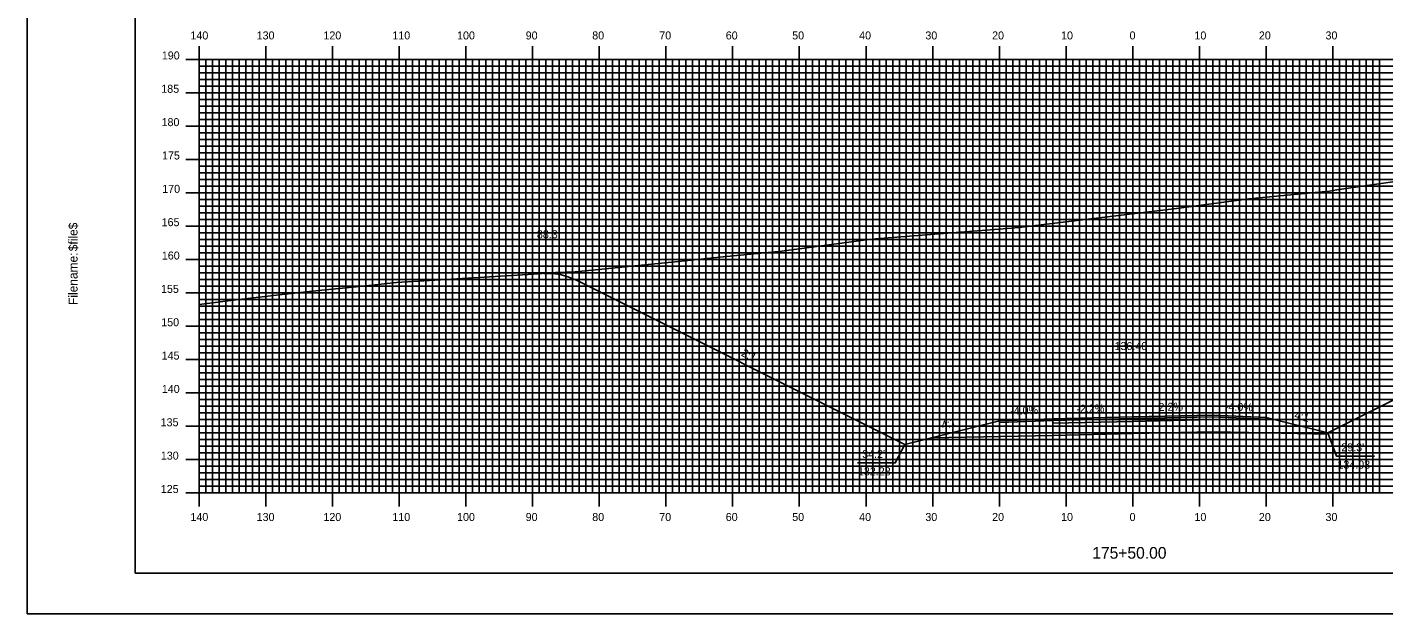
# Model space of a CAD drawing. Extents: x 1784221 to 1784564, y 442591 to 442811.
# Drawn here: x 1784221.2 to 1784424.7, y 442590.5 to 442678.5 of the extents above; entities that cross this region are included whole.
import ezdxf

# ---------------------------------------------------------------- set-up
doc = ezdxf.new("R2010")
doc.units = 0
for name, color, linetype in [('ANNOTATION', 7, 'Continuous'), ('BORDER', 7, 'Continuous'), ('D_Roadway_Centerline', 7, 'Continuous'), ('D_Roadway_Centerline_Text', 7, 'Continuous'), ('D_Roadway_Edge_Shoulder', 7, 'Continuous'), ('D_Roadway_Edge_TW', 7, 'Continuous'), ('D_Roadway_Pavement', 7, 'Continuous'), ('D_Roadway_SlopeLines', 7, 'Continuous'), ('D_Roadway_SubGrade', 7, 'Continuous'), ('D_Text_Standard', 7, 'Continuous'), ('H_V ANNOTATION', 7, 'Continuous'), ('MAJOR', 7, 'Continuous'), ('MINOR', 7, 'Continuous'), ('PLOT BOUNDARY', 7, 'Continuous'), ('S_Roadway_Centerline', 7, 'Continuous')]:
    doc.layers.add(name, color=color, linetype=linetype)

msp = doc.modelspace()

# ---------------------------------------------------------------- linework, layer by layer
at = {"layer": 'ANNOTATION'}
for points in [[(1784423.23, 442614.2), (1784417.54, 442614.2), (1784416.27, 442617.7)], [(1784345.7, 442613.18), (1784351.39, 442613.18), (1784352.83, 442615.94)]]:
    msp.add_lwpolyline(points, dxfattribs=at)
at = {"layer": 'BORDER'}
msp.add_lwpolyline([(1784237.4, 442596.67), (1784557.4, 442596.67), (1784557.4, 442806.67), (1784237.4, 442806.67)], close=True, dxfattribs=at)
at = {"layer": 'D_Roadway_Centerline'}
msp.add_lwpolyline([(1784298.69, 442641.6), (1784299.94, 442641.59), (1784301.19, 442641.41), (1784302.44, 442641.05), (1784303.69, 442640.51), (1784352.83, 442615.94), (1784356.83, 442616.94), (1784367, 442619.49), (1784375, 442619.81), (1784387, 442620.07), (1784399, 442620.33), (1784407, 442620.01), (1784416.27, 442617.7), (1784416.27, 442617.7), (1784509.11, 442664.11), (1784510.36, 442664.67), (1784511.61, 442665.1), (1784512.86, 442665.4), (1784514.11, 442665.56)], dxfattribs=at)
at = {"layer": 'D_Roadway_Edge_Shoulder'}
for points in [[(1784375, 442619.81), (1784367, 442619.49), (1784367, 442619.24), (1784375, 442619.56)], [(1784399, 442620.33), (1784407, 442620.01), (1784407, 442619.76), (1784399, 442620.08)]]:
    msp.add_lwpolyline(points, close=True, dxfattribs=at)
at = {"layer": 'D_Roadway_Edge_TW'}
msp.add_lwpolyline([(1784375, 442619.56), (1784375, 442619.81), (1784387, 442620.07), (1784399, 442620.33), (1784399, 442620.08), (1784387, 442619.82)], close=True, dxfattribs=at)
at = {"layer": 'D_Roadway_Pavement'}
msp.add_lwpolyline([(1784375, 442619.14), (1784375, 442619.56), (1784387, 442619.82), (1784399, 442620.08), (1784399, 442619.67), (1784387, 442619.4)], close=True, dxfattribs=at)
at = {"layer": 'D_Roadway_SlopeLines'}
for p in [(1784407, 442617.67), (1784416.27, 442617.7)]:
    msp.add_line(p, (1784416.27, 442617.49), dxfattribs=at)
for points in [[(1784416.27, 442617.7), (1784509.11, 442664.11), (1784510.36, 442664.67), (1784511.61, 442665.1), (1784512.86, 442665.4), (1784514.11, 442665.56)], [(1784352.83, 442615.94), (1784303.69, 442640.51), (1784302.44, 442641.05), (1784301.19, 442641.41), (1784299.94, 442641.59), (1784298.69, 442641.6)], [(1784367, 442619.49), (1784352.83, 442615.94)], [(1784407, 442620.01), (1784416.27, 442617.7)]]:
    msp.add_lwpolyline(points, dxfattribs=at)
at = {"layer": 'D_Roadway_SubGrade'}
msp.add_lwpolyline([(1784375, 442617.31), (1784356.83, 442616.94), (1784367, 442619.49), (1784367, 442619.24), (1784375, 442619.56), (1784387, 442619.82), (1784399, 442620.08), (1784407, 442619.76), (1784407, 442620.01), (1784407, 442617.67), (1784399, 442617.83), (1784387, 442617.57)], close=True, dxfattribs=at)
at = {"layer": 'MAJOR'}
for p, q in [((1784247, 442675.67), (1784247, 442673.67)), ((1784257, 442675.67), (1784257, 442673.67)), ((1784267, 442675.67), (1784267, 442673.67)), ((1784277, 442675.67), (1784277, 442673.67)), ((1784287, 442675.67), (1784287, 442673.67)), ((1784297, 442675.67), (1784297, 442673.67)), ((1784307, 442675.67), (1784307, 442673.67)), ((1784317, 442675.67), (1784317, 442673.67)), ((1784327, 442675.67), (1784327, 442673.67)), ((1784337, 442675.67), (1784337, 442673.67)), ((1784347, 442675.67), (1784347, 442673.67)), ((1784357, 442675.67), (1784357, 442673.67)), ((1784367, 442675.67), (1784367, 442673.67)), ((1784377, 442675.67), (1784377, 442673.67)), ((1784387, 442675.67), (1784387, 442673.67)), ((1784397, 442675.67), (1784397, 442673.67)), ((1784407, 442675.67), (1784407, 442673.67)), ((1784417, 442675.67), (1784417, 442673.67)), ((1784245, 442673.67), (1784247, 442673.67)), ((1784247, 442673.67), (1784527, 442673.67)), ((1784247, 442608.67), (1784247, 442673.67)), ((1784247, 442608.67), (1784247, 442673.67)), ((1784247, 442673.67), (1784527, 442673.67)), ((1784257, 442608.67), (1784257, 442673.67)), ((1784267, 442608.67), (1784267, 442673.67)), ((1784277, 442608.67), (1784277, 442673.67)), ((1784287, 442608.67), (1784287, 442673.67)), ((1784297, 442608.67), (1784297, 442673.67)), ((1784307, 442608.67), (1784307, 442673.67)), ((1784317, 442608.67), (1784317, 442673.67)), ((1784327, 442608.67), (1784327, 442673.67)), ((1784337, 442608.67), (1784337, 442673.67)), ((1784347, 442608.67), (1784347, 442673.67)), ((1784357, 442608.67), (1784357, 442673.67)), ((1784367, 442608.67), (1784367, 442673.67)), ((1784377, 442608.67), (1784377, 442673.67)), ((1784387, 442608.67), (1784387, 442673.67)), ((1784397, 442608.67), (1784397, 442673.67)), ((1784407, 442608.67), (1784407, 442673.67)), ((1784417, 442608.67), (1784417, 442673.67)), ((1784245, 442668.67), (1784247, 442668.67)), ((1784247, 442668.67), (1784527, 442668.67)), ((1784245, 442663.67), (1784247, 442663.67)), ((1784247, 442663.67), (1784527, 442663.67)), ((1784245, 442658.67), (1784247, 442658.67)), ((1784247, 442658.67), (1784527, 442658.67)), ((1784245, 442653.67), (1784247, 442653.67)), ((1784247, 442653.67), (1784527, 442653.67)), ((1784245, 442648.67), (1784247, 442648.67)), ((1784247, 442648.67), (1784527, 442648.67)), ((1784245, 442643.67), (1784247, 442643.67)), ((1784247, 442643.67), (1784527, 442643.67)), ((1784245, 442638.67), (1784247, 442638.67)), ((1784247, 442638.67), (1784527, 442638.67)), ((1784245, 442633.67), (1784247, 442633.67)), ((1784247, 442633.67), (1784527, 442633.67)), ((1784245, 442628.67), (1784247, 442628.67)), ((1784247, 442628.67), (1784527, 442628.67)), ((1784245, 442623.67), (1784247, 442623.67)), ((1784247, 442623.67), (1784527, 442623.67)), ((1784245, 442618.67), (1784247, 442618.67)), ((1784247, 442618.67), (1784527, 442618.67)), ((1784245, 442613.67), (1784247, 442613.67)), ((1784247, 442613.67), (1784527, 442613.67)), ((1784245, 442608.67), (1784247, 442608.67)), ((1784247, 442608.67), (1784527, 442608.67)), ((1784247, 442608.67), (1784527, 442608.67)), ((1784247, 442606.66), (1784247, 442608.67)), ((1784257, 442606.66), (1784257, 442608.67)), ((1784267, 442606.66), (1784267, 442608.67)), ((1784277, 442606.66), (1784277, 442608.67)), ((1784287, 442606.66), (1784287, 442608.67)), ((1784297, 442606.66), (1784297, 442608.67)), ((1784307, 442606.66), (1784307, 442608.67)), ((1784317, 442606.66), (1784317, 442608.67)), ((1784327, 442606.66), (1784327, 442608.67)), ((1784337, 442606.66), (1784337, 442608.67)), ((1784347, 442606.66), (1784347, 442608.67)), ((1784357, 442606.66), (1784357, 442608.67)), ((1784367, 442606.66), (1784367, 442608.67)), ((1784377, 442606.66), (1784377, 442608.67)), ((1784387, 442606.66), (1784387, 442608.67)), ((1784397, 442606.66), (1784397, 442608.67)), ((1784407, 442606.66), (1784407, 442608.67)), ((1784417, 442606.66), (1784417, 442608.67))]:
    msp.add_line(p, q, dxfattribs=at)
at = {"layer": 'MINOR'}
for p, q in [((1784248, 442608.67), (1784248, 442673.67)), ((1784249, 442608.67), (1784249, 442673.67)), ((1784250, 442608.67), (1784250, 442673.67)), ((1784251, 442608.67), (1784251, 442673.67)), ((1784252, 442608.67), (1784252, 442673.67)), ((1784253, 442608.67), (1784253, 442673.67)), ((1784254, 442608.67), (1784254, 442673.67)), ((1784255, 442608.67), (1784255, 442673.67)), ((1784256, 442608.67), (1784256, 442673.67)), ((1784258, 442608.67), (1784258, 442673.67)), ((1784259, 442608.67), (1784259, 442673.67)), ((1784260, 442608.67), (1784260, 442673.67)), ((1784261, 442608.67), (1784261, 442673.67)), ((1784262, 442608.67), (1784262, 442673.67)), ((1784263, 442608.67), (1784263, 442673.67)), ((1784264, 442608.67), (1784264, 442673.67)), ((1784265, 442608.67), (1784265, 442673.67)), ((1784266, 442608.67), (1784266, 442673.67)), ((1784268, 442608.67), (1784268, 442673.67)), ((1784269, 442608.67), (1784269, 442673.67)), ((1784270, 442608.67), (1784270, 442673.67)), ((1784271, 442608.67), (1784271, 442673.67)), ((1784272, 442608.67), (1784272, 442673.67)), ((1784273, 442608.67), (1784273, 442673.67)), ((1784274, 442608.67), (1784274, 442673.67)), ((1784275, 442608.67), (1784275, 442673.67)), ((1784276, 442608.67), (1784276, 442673.67)), ((1784278, 442608.67), (1784278, 442673.67)), ((1784279, 442608.67), (1784279, 442673.67)), ((1784280, 442608.67), (1784280, 442673.67)), ((1784281, 442608.67), (1784281, 442673.67)), ((1784282, 442608.67), (1784282, 442673.67)), ((1784283, 442608.67), (1784283, 442673.67)), ((1784284, 442608.67), (1784284, 442673.67)), ((1784285, 442608.67), (1784285, 442673.67)), ((1784286, 442608.67), (1784286, 442673.67)), ((1784288, 442608.67), (1784288, 442673.67)), ((1784289, 442608.67), (1784289, 442673.67)), ((1784290, 442608.67), (1784290, 442673.67)), ((1784291, 442608.67), (1784291, 442673.67)), ((1784292, 442608.67), (1784292, 442673.67)), ((1784293, 442608.67), (1784293, 442673.67)), ((1784294, 442608.67), (1784294, 442673.67)), ((1784295, 442608.67), (1784295, 442673.67)), ((1784296, 442608.67), (1784296, 442673.67)), ((1784298, 442608.67), (1784298, 442673.67)), ((1784299, 442608.67), (1784299, 442673.67)), ((1784300, 442608.67), (1784300, 442673.67)), ((1784301, 442608.67), (1784301, 442673.67)), ((1784302, 442608.67), (1784302, 442673.67)), ((1784303, 442608.67), (1784303, 442673.67)), ((1784304, 442608.67), (1784304, 442673.67)), ((1784305, 442608.67), (1784305, 442673.67)), ((1784306, 442608.67), (1784306, 442673.67)), ((1784308, 442608.67), (1784308, 442673.67)), ((1784309, 442608.67), (1784309, 442673.67)), ((1784310, 442608.67), (1784310, 442673.67)), ((1784311, 442608.67), (1784311, 442673.67)), ((1784312, 442608.67), (1784312, 442673.67)), ((1784313, 442608.67), (1784313, 442673.67)), ((1784314, 442608.67), (1784314, 442673.67)), ((1784315, 442608.67), (1784315, 442673.67)), ((1784316, 442608.67), (1784316, 442673.67)), ((1784318, 442608.67), (1784318, 442673.67)), ((1784319, 442608.67), (1784319, 442673.67)), ((1784320, 442608.67), (1784320, 442673.67)), ((1784321, 442608.67), (1784321, 442673.67)), ((1784322, 442608.67), (1784322, 442673.67)), ((1784323, 442608.67), (1784323, 442673.67)), ((1784324, 442608.67), (1784324, 442673.67)), ((1784325, 442608.67), (1784325, 442673.67)), ((1784326, 442608.67), (1784326, 442673.67)), ((1784328, 442608.67), (1784328, 442673.67)), ((1784329, 442608.67), (1784329, 442673.67)), ((1784330, 442608.67), (1784330, 442673.67)), ((1784331, 442608.67), (1784331, 442673.67)), ((1784332, 442608.67), (1784332, 442673.67)), ((1784333, 442608.67), (1784333, 442673.67)), ((1784334, 442608.67), (1784334, 442673.67)), ((1784335, 442608.67), (1784335, 442673.67)), ((1784336, 442608.67), (1784336, 442673.67)), ((1784338, 442608.67), (1784338, 442673.67)), ((1784339, 442608.67), (1784339, 442673.67)), ((1784340, 442608.67), (1784340, 442673.67)), ((1784341, 442608.67), (1784341, 442673.67)), ((1784342, 442608.67), (1784342, 442673.67)), ((1784343, 442608.67), (1784343, 442673.67)), ((1784344, 442608.67), (1784344, 442673.67)), ((1784345, 442608.67), (1784345, 442673.67)), ((1784346, 442608.67), (1784346, 442673.67)), ((1784348, 442608.67), (1784348, 442673.67)), ((1784349, 442608.67), (1784349, 442673.67)), ((1784350, 442608.67), (1784350, 442673.67)), ((1784351, 442608.67), (1784351, 442673.67)), ((1784352, 442608.67), (1784352, 442673.67)), ((1784353, 442608.67), (1784353, 442673.67)), ((1784354, 442608.67), (1784354, 442673.67)), ((1784355, 442608.67), (1784355, 442673.67)), ((1784356, 442608.67), (1784356, 442673.67)), ((1784358, 442608.67), (1784358, 442673.67)), ((1784359, 442608.67), (1784359, 442673.67)), ((1784360, 442608.67), (1784360, 442673.67)), ((1784361, 442608.67), (1784361, 442673.67)), ((1784362, 442608.67), (1784362, 442673.67)), ((1784363, 442608.67), (1784363, 442673.67)), ((1784364, 442608.67), (1784364, 442673.67)), ((1784365, 442608.67), (1784365, 442673.67)), ((1784366, 442608.67), (1784366, 442673.67)), ((1784368, 442608.67), (1784368, 442673.67)), ((1784369, 442608.67), (1784369, 442673.67)), ((1784370, 442608.67), (1784370, 442673.67)), ((1784371, 442608.67), (1784371, 442673.67)), ((1784372, 442608.67), (1784372, 442673.67)), ((1784373, 442608.67), (1784373, 442673.67)), ((1784374, 442608.67), (1784374, 442673.67)), ((1784375, 442608.67), (1784375, 442673.67)), ((1784376, 442608.67), (1784376, 442673.67)), ((1784378, 442608.67), (1784378, 442673.67)), ((1784379, 442608.67), (1784379, 442673.67)), ((1784380, 442608.67), (1784380, 442673.67)), ((1784381, 442608.67), (1784381, 442673.67)), ((1784382, 442608.67), (1784382, 442673.67)), ((1784383, 442608.67), (1784383, 442673.67)), ((1784384, 442608.67), (1784384, 442673.67)), ((1784385, 442608.67), (1784385, 442673.67)), ((1784386, 442608.67), (1784386, 442673.67)), ((1784388, 442608.67), (1784388, 442673.67)), ((1784389, 442608.67), (1784389, 442673.67)), ((1784390, 442608.67), (1784390, 442673.67)), ((1784391, 442608.67), (1784391, 442673.67)), ((1784392, 442608.67), (1784392, 442673.67)), ((1784393, 442608.67), (1784393, 442673.67)), ((1784394, 442608.67), (1784394, 442673.67)), ((1784395, 442608.67), (1784395, 442673.67)), ((1784396, 442608.67), (1784396, 442673.67)), ((1784398, 442608.67), (1784398, 442673.67)), ((1784399, 442608.67), (1784399, 442673.67)), ((1784400, 442608.67), (1784400, 442673.67)), ((1784401, 442608.67), (1784401, 442673.67)), ((1784402, 442608.67), (1784402, 442673.67)), ((1784403, 442608.67), (1784403, 442673.67)), ((1784404, 442608.67), (1784404, 442673.67)), ((1784405, 442608.67), (1784405, 442673.67)), ((1784406, 442608.67), (1784406, 442673.67)), ((1784408, 442608.67), (1784408, 442673.67)), ((1784409, 442608.67), (1784409, 442673.67)), ((1784410, 442608.67), (1784410, 442673.67)), ((1784411, 442608.67), (1784411, 442673.67)), ((1784412, 442608.67), (1784412, 442673.67)), ((1784413, 442608.67), (1784413, 442673.67)), ((1784414, 442608.67), (1784414, 442673.67)), ((1784415, 442608.67), (1784415, 442673.67)), ((1784416, 442608.67), (1784416, 442673.67)), ((1784418, 442608.67), (1784418, 442673.67)), ((1784419, 442608.67), (1784419, 442673.67)), ((1784420, 442608.67), (1784420, 442673.67)), ((1784421, 442608.67), (1784421, 442673.67)), ((1784422, 442608.67), (1784422, 442673.67)), ((1784423, 442608.67), (1784423, 442673.67)), ((1784424, 442608.67), (1784424, 442673.67)), ((1784247, 442672.67), (1784527, 442672.67)), ((1784247, 442672.67), (1784249, 442672.67)), ((1784247, 442671.67), (1784527, 442671.67)), ((1784247, 442671.67), (1784249, 442671.67)), ((1784247, 442670.67), (1784527, 442670.67)), ((1784247, 442670.67), (1784249, 442670.67)), ((1784247, 442669.67), (1784527, 442669.67)), ((1784247, 442669.67), (1784249, 442669.67)), ((1784247, 442667.67), (1784527, 442667.67)), ((1784247, 442667.67), (1784249, 442667.67)), ((1784247, 442666.67), (1784527, 442666.67)), ((1784247, 442666.67), (1784249, 442666.67)), ((1784247, 442665.67), (1784527, 442665.67)), ((1784247, 442665.67), (1784249, 442665.67)), ((1784247, 442664.67), (1784527, 442664.67)), ((1784247, 442664.67), (1784249, 442664.67)), ((1784247, 442662.67), (1784527, 442662.67)), ((1784247, 442662.67), (1784249, 442662.67)), ((1784247, 442661.67), (1784527, 442661.67)), ((1784247, 442661.67), (1784249, 442661.67)), ((1784247, 442660.67), (1784527, 442660.67)), ((1784247, 442660.67), (1784249, 442660.67)), ((1784247, 442659.67), (1784527, 442659.67)), ((1784247, 442659.67), (1784249, 442659.67)), ((1784247, 442657.67), (1784527, 442657.67)), ((1784247, 442657.67), (1784249, 442657.67)), ((1784247, 442656.67), (1784527, 442656.67)), ((1784247, 442656.67), (1784249, 442656.67)), ((1784247, 442655.67), (1784527, 442655.67)), ((1784247, 442655.67), (1784249, 442655.67)), ((1784247, 442654.67), (1784527, 442654.67)), ((1784247, 442654.67), (1784249, 442654.67)), ((1784247, 442652.67), (1784527, 442652.67)), ((1784247, 442652.67), (1784249, 442652.67)), ((1784247, 442651.67), (1784527, 442651.67)), ((1784247, 442651.67), (1784249, 442651.67)), ((1784247, 442650.67), (1784527, 442650.67)), ((1784247, 442650.67), (1784249, 442650.67)), ((1784247, 442649.67), (1784527, 442649.67)), ((1784247, 442649.67), (1784249, 442649.67)), ((1784247, 442647.67), (1784527, 442647.67)), ((1784247, 442647.67), (1784249, 442647.67)), ((1784247, 442646.67), (1784527, 442646.67)), ((1784247, 442646.67), (1784249, 442646.67)), ((1784247, 442645.67), (1784527, 442645.67)), ((1784247, 442645.67), (1784249, 442645.67)), ((1784247, 442644.67), (1784527, 442644.67)), ((1784247, 442644.67), (1784249, 442644.67)), ((1784247, 442642.67), (1784527, 442642.67)), ((1784247, 442642.67), (1784249, 442642.67)), ((1784247, 442641.67), (1784527, 442641.67)), ((1784247, 442641.67), (1784249, 442641.67)), ((1784247, 442640.67), (1784527, 442640.67)), ((1784247, 442640.67), (1784249, 442640.67)), ((1784247, 442639.67), (1784527, 442639.67)), ((1784247, 442639.67), (1784249, 442639.67)), ((1784247, 442637.67), (1784527, 442637.67)), ((1784247, 442637.67), (1784249, 442637.67)), ((1784247, 442636.67), (1784527, 442636.67)), ((1784247, 442636.67), (1784249, 442636.67)), ((1784247, 442635.67), (1784527, 442635.67)), ((1784247, 442635.67), (1784249, 442635.67)), ((1784247, 442634.67), (1784527, 442634.67)), ((1784247, 442634.67), (1784249, 442634.67)), ((1784247, 442632.67), (1784527, 442632.67)), ((1784247, 442632.67), (1784249, 442632.67)), ((1784247, 442631.67), (1784527, 442631.67)), ((1784247, 442631.67), (1784249, 442631.67)), ((1784247, 442630.67), (1784527, 442630.67)), ((1784247, 442630.67), (1784249, 442630.67)), ((1784247, 442629.67), (1784527, 442629.67)), ((1784247, 442629.67), (1784249, 442629.67)), ((1784247, 442627.67), (1784527, 442627.67)), ((1784247, 442627.67), (1784249, 442627.67)), ((1784247, 442626.67), (1784527, 442626.67)), ((1784247, 442626.67), (1784249, 442626.67)), ((1784247, 442625.67), (1784527, 442625.67)), ((1784247, 442625.67), (1784249, 442625.67)), ((1784247, 442624.67), (1784527, 442624.67)), ((1784247, 442624.67), (1784249, 442624.67)), ((1784247, 442622.67), (1784527, 442622.67)), ((1784247, 442622.67), (1784249, 442622.67)), ((1784247, 442621.67), (1784527, 442621.67)), ((1784247, 442621.67), (1784249, 442621.67)), ((1784247, 442620.67), (1784527, 442620.67)), ((1784247, 442620.67), (1784249, 442620.67)), ((1784247, 442619.67), (1784527, 442619.67)), ((1784247, 442619.67), (1784249, 442619.67)), ((1784247, 442617.67), (1784527, 442617.67)), ((1784247, 442617.67), (1784249, 442617.67)), ((1784247, 442616.67), (1784527, 442616.67)), ((1784247, 442616.67), (1784249, 442616.67)), ((1784247, 442615.67), (1784527, 442615.67)), ((1784247, 442615.67), (1784249, 442615.67)), ((1784247, 442614.67), (1784527, 442614.67)), ((1784247, 442614.67), (1784249, 442614.67)), ((1784247, 442612.67), (1784527, 442612.67)), ((1784247, 442612.67), (1784249, 442612.67)), ((1784247, 442611.67), (1784527, 442611.67)), ((1784247, 442611.67), (1784249, 442611.67)), ((1784247, 442610.67), (1784527, 442610.67)), ((1784247, 442610.67), (1784249, 442610.67)), ((1784247, 442609.67), (1784527, 442609.67)), ((1784247, 442609.67), (1784249, 442609.67))]:
    msp.add_line(p, q, dxfattribs=at)
at = {"layer": 'PLOT BOUNDARY'}
msp.add_lwpolyline([(1784221.21, 442590.55), (1784561.21, 442590.55), (1784561.21, 442810.55), (1784221.21, 442810.55)], close=True, dxfattribs=at)
at = {"layer": 'S_Roadway_Centerline'}
msp.add_lwpolyline([(1784247, 442636.94), (1784252.54, 442637.62), (1784259.44, 442638.45), (1784265.41, 442639.07), (1784271.06, 442639.65), (1784276.61, 442640.21), (1784297.14, 442641.48), (1784300.43, 442641.73), (1784303.39, 442641.85), (1784319.34, 442643.44), (1784325.57, 442644.1), (1784334.4, 442644.94), (1784345.17, 442646.38), (1784346.95, 442646.61), (1784348.44, 442646.75), (1784368.81, 442648.38), (1784370.39, 442648.5), (1784393.18, 442651.26), (1784393.54, 442651.31), (1784404.4, 442652.79), (1784415.4, 442653.8), (1784416.51, 442653.94), (1784417.59, 442654.11), (1784436.83, 442656.85)], dxfattribs=at)

# ---------------------------------------------------------------- texts
at = {"layer": 'ANNOTATION'}
for s, rotation, p in [('2:1', 333.4349, (1784328.19, 442629.29)), ('-4.0%', 2.2906, (1784368.63, 442620.35)), ('-2.2%', 1.2603, (1784378.56, 442620.68)), ('2.2%', 1.2603, (1784390.88, 442620.96)), ('-4.0%', 357.7094, (1784400.79, 442621.06)), ('4:1', 345.9638, (1784411.14, 442619.84)), ('4:1', 14.0362, (1784358.45, 442618.21))]:
    msp.add_text(s, height=1.2, rotation=rotation, dxfattribs=at).set_placement(p)
for s, p in [("34.2'", (1784346.43, 442613.91)), ("29.3'", (1784418.27, 442614.92)), ('132.28', (1784345.79, 442611.31)), ('134.03', (1784417.69, 442612.32))]:
    msp.add_text(s, height=1.2, dxfattribs=at).set_placement(p)
at = {"layer": 'BORDER'}
for s, p in [('$file$', (1784228.77, 442644.92)), ('$file$', (1784228.77, 442644.92)), ('Filename:', (1784228.77, 442636.86)), ('Filename:', (1784228.77, 442636.86))]:
    msp.add_text(s, height=1.339, rotation=90, dxfattribs=at).set_placement(p)
at = {"layer": 'D_Roadway_Centerline'}
for s, p in [('C', (1784386.99, 442620.07)), ('L', (1784387, 442620.06))]:
    msp.add_text(s, height=0.0146, dxfattribs=at).set_placement(p)
at = {"layer": 'D_Roadway_Centerline_Text'}
msp.add_text('136.40', height=1.2, dxfattribs=at).set_placement((1784384.27, 442630.1))
at = {"layer": 'D_Text_Standard'}
msp.add_text("88.3'", height=1.2, dxfattribs=at).set_placement((1784297.65, 442646.86))
at = {"layer": 'H_V ANNOTATION'}
for s, height, p in [('140', 1.2, (1784245.7, 442676.67)), ('130', 1.2, (1784255.63, 442676.67)), ('120', 1.2, (1784265.64, 442676.67)), ('110', 1.2, (1784275.98, 442676.67)), ('100', 1.2, (1784285.68, 442676.67)), ('90', 1.2, (1784295.97, 442676.67)), ('80', 1.2, (1784305.95, 442676.67)), ('70', 1.2, (1784316, 442676.67)), ('60', 1.2, (1784325.97, 442676.67)), ('50', 1.2, (1784335.93, 442676.67)), ('40', 1.2, (1784345.97, 442676.67)), ('30', 1.2, (1784355.9, 442676.67)), ('20', 1.2, (1784365.91, 442676.67)), ('10', 1.2, (1784376.25, 442676.67)), ('0', 1.2, (1784386.52, 442676.67)), ('10', 1.2, (1784396.25, 442676.67)), ('20', 1.2, (1784405.91, 442676.67)), ('30', 1.2, (1784415.9, 442676.67)), ('190', 1.2, (1784241.41, 442673.67)), ('185', 1.2, (1784241.33, 442668.67)), ('180', 1.2, (1784241.37, 442663.67)), ('175', 1.2, (1784241.44, 442658.67)), ('170', 1.2, (1784241.47, 442653.67)), ('165', 1.2, (1784241.38, 442648.67)), ('160', 1.2, (1784241.41, 442643.67)), ('155', 1.2, (1784241.29, 442638.67)), ('150', 1.2, (1784241.32, 442633.67)), ('145', 1.2, (1784241.38, 442628.67)), ('140', 1.2, (1784241.41, 442623.67)), ('135', 1.2, (1784241.23, 442618.67)), ('130', 1.2, (1784241.26, 442613.67)), ('125', 1.2, (1784241.25, 442608.67)), ('140', 1.2, (1784245.7, 442604.47)), ('130', 1.2, (1784255.63, 442604.47)), ('120', 1.2, (1784265.64, 442604.47)), ('110', 1.2, (1784275.98, 442604.47)), ('100', 1.2, (1784285.68, 442604.47)), ('90', 1.2, (1784295.97, 442604.47)), ('80', 1.2, (1784305.95, 442604.47)), ('70', 1.2, (1784316, 442604.47)), ('60', 1.2, (1784325.97, 442604.47)), ('50', 1.2, (1784335.93, 442604.47)), ('40', 1.2, (1784345.97, 442604.47)), ('30', 1.2, (1784355.9, 442604.47)), ('20', 1.2, (1784365.91, 442604.47)), ('10', 1.2, (1784376.25, 442604.47)), ('0', 1.2, (1784386.52, 442604.47)), ('10', 1.2, (1784396.25, 442604.47)), ('20', 1.2, (1784405.91, 442604.47)), ('30', 1.2, (1784415.9, 442604.47)), ('175+50.00', 1.75, (1784380.93, 442598.82))]:
    msp.add_text(s, height=height, dxfattribs=at).set_placement(p)
at = {"layer": 'MAJOR'}
msp.add_text('-', height=0.012, dxfattribs=at).set_placement((1784246.99, 442608.67))

doc.saveas('drawing.dxf')
